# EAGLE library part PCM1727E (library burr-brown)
SoundPlus(TM) Stereo Audio DAC with Programmable Dual PLL
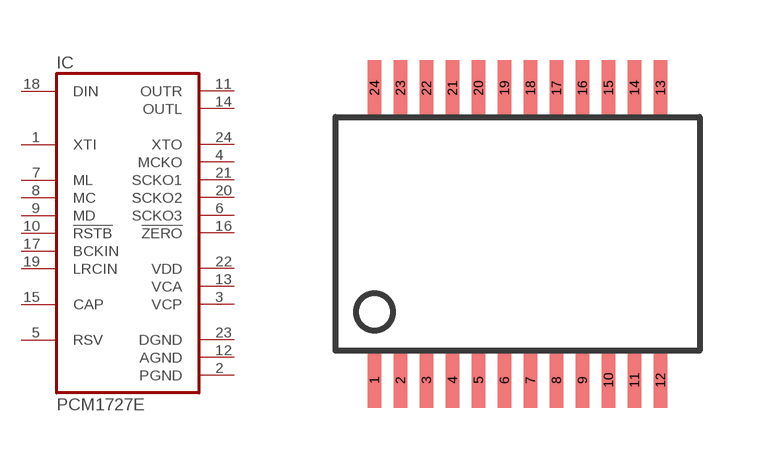
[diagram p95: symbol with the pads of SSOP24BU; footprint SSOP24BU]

Designator prefix IC

## PCM1727E (MF: TEXAS INSTRUMENT CONNECTORS; MPN: PCM1727E; OC_FARNELL: 1408314; OC_NEWARK: 75C5319)  [SSOP24BU]
1  XTI  in
2  PGND  pwr
3  VCP  pwr
4  MCKO  out
5  RSV  pas
6  SCKO3  out
7  ML  in
8  MC  in
9  MD  in
10  !RSTB  in
11  OUTR  out
12  AGND  pwr
13  VCA  pwr
14  OUTL  out
15  CAP  pas
16  !ZERO  out
17  BCKIN  in
18  DIN  in
19  LRCIN  in
20  SCKO2  out
21  SCKO1  out
22  VDD  pwr
23  DGND  pwr
24  XTO  out

## Footprint SSOP24BU (pad centres in mm)
Small Shrink Outline Package
smd 0.348 x 1.397: 1 -3.575,-3.656; 2 -2.925,-3.656; 3 -2.275,-3.656; 4 -1.625,-3.656; 5 -0.975,-3.656; 6 -0.325,-3.656; 7 0.325,-3.656; 8 0.975,-3.656; 9 1.625,-3.656; 10 2.275,-3.656; 11 2.925,-3.656; 12 3.575,-3.656; 13 3.575,3.656; 14 2.925,3.656; 15 2.275,3.656; 16 1.625,3.656; 17 0.975,3.656; 18 0.325,3.656; 19 -0.325,3.656; 20 -0.975,3.656; 21 -1.625,3.656; 22 -2.275,3.656; 23 -2.925,3.656; 24 -3.575,3.656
